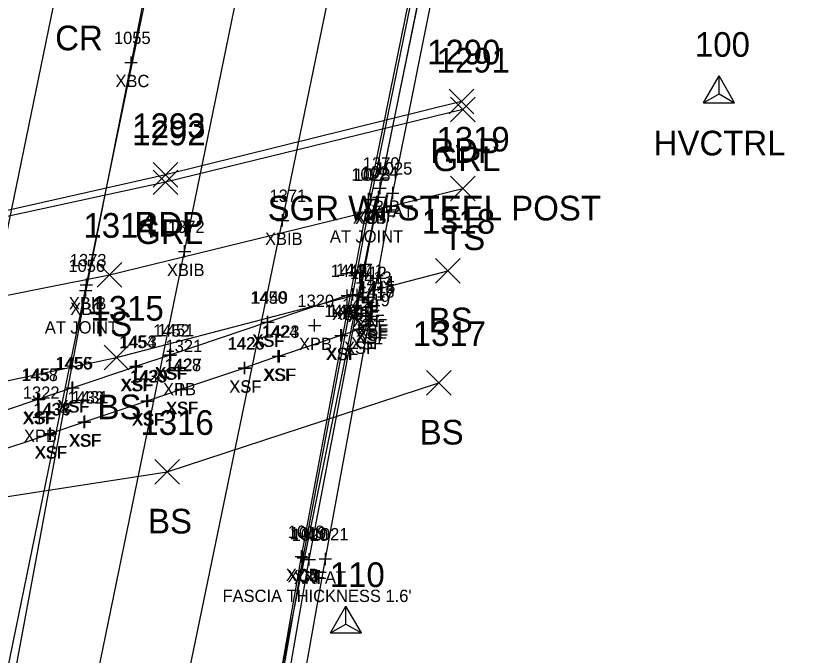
# Model space of a CAD drawing. Extents: x 1683147 to 1683637, y 416837 to 418211.
# Drawn here: x 1683315.4 to 1683379.1, y 417492.2 to 417544.1 of the extents above; entities that cross this region are included whole.
import ezdxf

# ---------------------------------------------------------------- set-up
doc = ezdxf.new("R2010")
doc.units = 0
for name, color, linetype in [('B_A', 7, 'Continuous'), ('B_C', 7, 'Continuous'), ('B_I', 7, 'Continuous'), ('B_TIC', 7, 'Continuous'), ('BB', 7, 'Continuous'), ('BDC', 7, 'Continuous'), ('BDEFAULT', 7, 'Continuous'), ('BELB', 7, 'Continuous'), ('BF', 7, 'Continuous'), ('BR', 7, 'Continuous'), ('C_A', 7, 'Continuous'), ('C_I', 7, 'Continuous'), ('CPSM', 7, 'Continuous'), ('L_A', 7, 'Continuous'), ('L_I', 7, 'Continuous'), ('L_TIC', 7, 'Continuous'), ('LELB', 7, 'Continuous'), ('P_A', 7, 'Continuous'), ('P_I', 7, 'Continuous'), ('P_TIC', 7, 'Continuous'), ('PET', 7, 'Continuous'), ('R_A', 7, 'Continuous'), ('R_C', 7, 'Continuous'), ('R_I', 7, 'Continuous'), ('R_TIC', 7, 'Continuous'), ('RGR', 7, 'Continuous')]:
    doc.layers.add(name, color=color, linetype=linetype)

msp = doc.modelspace()

# ---------------------------------------------------------------- linework, layer by layer
at = {"layer": 'B_TIC'}
for p, q in [((1683324.715, 417540.29), (1683324.791, 417540.29)), ((1683344.921, 417530.101), (1683344.996, 417530.101)), ((1683344.8, 417529.377), (1683344.875, 417529.377)), ((1683345.954, 417529.699), (1683346.03, 417529.699)), ((1683343.975, 417529.208), (1683344.05, 417529.208)), ((1683344.182, 417529.185), (1683344.258, 417529.185)), ((1683337.021, 417527.483), (1683337.096, 417527.483)), ((1683329.062, 417524.964), (1683329.137, 417524.964)), ((1683321.047, 417521.799), (1683321.122, 417521.799)), ((1683321.099, 417522.255), (1683321.175, 417522.255)), ((1683342.26, 417521.384), (1683342.336, 417521.384)), ((1683342.703, 417521.474), (1683342.778, 417521.474)), ((1683343.053, 417521.439), (1683343.129, 417521.439)), ((1683343.053, 417521.439), (1683343.129, 417521.439)), ((1683343.552, 417521.224), (1683343.627, 417521.224)), ((1683343.95, 417520.833), (1683344.026, 417520.833)), ((1683344.15, 417520.48), (1683344.225, 417520.48)), ((1683344.244, 417520.054), (1683344.32, 417520.054)), ((1683335.781, 417519.216), (1683335.857, 417519.216)), ((1683335.822, 417519.23), (1683335.897, 417519.23)), ((1683344.153, 417519.468), (1683344.229, 417519.468)), ((1683344.217, 417519.713), (1683344.293, 417519.713)), ((1683339.608, 417518.956), (1683339.684, 417518.956)), ((1683343.243, 417518.65), (1683343.318, 417518.65)), ((1683343.808, 417519.011), (1683343.883, 417519.011)), ((1683341.749, 417518.142), (1683341.825, 417518.142)), ((1683341.818, 417518.147), (1683341.893, 417518.147)), ((1683327.864, 417516.543), (1683327.939, 417516.543)), ((1683327.935, 417516.576), (1683328.01, 417516.576)), ((1683336.669, 417516.454), (1683336.745, 417516.454)), ((1683336.761, 417516.455), (1683336.837, 417516.455)), ((1683325.085, 417515.608), (1683325.16, 417515.608)), ((1683325.172, 417515.648), (1683325.248, 417515.648)), ((1683333.924, 417515.49), (1683333.999, 417515.49)), ((1683333.939, 417515.509), (1683334.015, 417515.509)), ((1683328.581, 417515.289), (1683328.656, 417515.289)), ((1683319.943, 417513.882), (1683320.018, 417513.882)), ((1683320, 417513.899), (1683320.075, 417513.899)), ((1683328.774, 417513.745), (1683328.85, 417513.745)), ((1683328.825, 417513.773), (1683328.9, 417513.773)), ((1683317.155, 417512.94), (1683317.23, 417512.94)), ((1683317.244, 417512.976), (1683317.32, 417512.976)), ((1683326.011, 417512.818), (1683326.087, 417512.818)), ((1683326.076, 417512.847), (1683326.152, 417512.847)), ((1683317.287, 417511.503), (1683317.363, 417511.503)), ((1683320.9, 417511.111), (1683320.976, 417511.111)), ((1683320.968, 417511.137), (1683321.043, 417511.137)), ((1683318.125, 417510.144), (1683318.201, 417510.144)), ((1683318.184, 417510.177), (1683318.259, 417510.177)), ((1683338.542, 417500.213), (1683338.617, 417500.213)), ((1683338.695, 417500.106), (1683338.77, 417500.106)), ((1683339.173, 417499.968), (1683339.249, 417499.968)), ((1683340.486, 417500.015), (1683340.561, 417500.015))]:
    msp.add_line(p, q, dxfattribs=at)
for points in [[(1683324.212, 417540.29), (1683325.212, 417540.29)], [(1683324.712, 417539.79), (1683324.712, 417540.79)], [(1683344.417, 417530.101), (1683345.417, 417530.101)], [(1683344.917, 417529.601), (1683344.917, 417530.601)], [(1683345.951, 417529.199), (1683345.951, 417530.199)], [(1683343.971, 417528.708), (1683343.971, 417529.708)], [(1683344.179, 417528.685), (1683344.179, 417529.685)], [(1683344.296, 417529.377), (1683345.296, 417529.377)], [(1683344.796, 417528.877), (1683344.796, 417529.877)], [(1683345.451, 417529.699), (1683346.451, 417529.699)], [(1683343.471, 417529.208), (1683344.471, 417529.208)], [(1683343.679, 417529.185), (1683344.679, 417529.185)], [(1683336.517, 417527.483), (1683337.517, 417527.483)], [(1683337.017, 417526.983), (1683337.017, 417527.983)], [(1683328.558, 417524.964), (1683329.558, 417524.964)], [(1683329.058, 417524.464), (1683329.058, 417525.464)], [(1683321.096, 417521.755), (1683321.096, 417522.755)], [(1683320.543, 417521.799), (1683321.543, 417521.799)], [(1683320.596, 417522.255), (1683321.596, 417522.255)], [(1683321.043, 417521.299), (1683321.043, 417522.3)], [(1683342.257, 417520.884), (1683342.257, 417521.884)], [(1683342.699, 417520.974), (1683342.699, 417521.974)], [(1683343.05, 417520.939), (1683343.05, 417521.939)], [(1683343.05, 417520.939), (1683343.05, 417521.939)], [(1683343.548, 417520.724), (1683343.548, 417521.724)], [(1683341.757, 417521.384), (1683342.757, 417521.384)], [(1683342.199, 417521.474), (1683343.199, 417521.474)], [(1683342.55, 417521.439), (1683343.55, 417521.439)], [(1683342.55, 417521.439), (1683343.55, 417521.439)], [(1683343.048, 417521.224), (1683344.048, 417521.224)], [(1683343.947, 417520.333), (1683343.947, 417521.333)], [(1683343.447, 417520.833), (1683344.447, 417520.833)], [(1683343.646, 417520.48), (1683344.646, 417520.48)], [(1683344.146, 417519.98), (1683344.146, 417520.98)], [(1683344.241, 417519.554), (1683344.241, 417520.554)], [(1683343.741, 417520.054), (1683344.741, 417520.054)], [(1683344.15, 417518.968), (1683344.15, 417519.968)], [(1683344.214, 417519.213), (1683344.214, 417520.213)], [(1683335.278, 417519.216), (1683336.278, 417519.216)], [(1683335.318, 417519.23), (1683336.318, 417519.23)], [(1683335.778, 417518.716), (1683335.778, 417519.716)], [(1683335.818, 417518.73), (1683335.818, 417519.73)], [(1683339.605, 417518.456), (1683339.605, 417519.456)], [(1683343.239, 417518.15), (1683343.239, 417519.15)], [(1683343.65, 417519.468), (1683344.65, 417519.468)], [(1683343.714, 417519.713), (1683344.714, 417519.713)], [(1683343.804, 417518.511), (1683343.804, 417519.511)], [(1683339.105, 417518.956), (1683340.105, 417518.956)], [(1683341.746, 417517.642), (1683341.746, 417518.642)], [(1683341.814, 417517.647), (1683341.814, 417518.647)], [(1683342.739, 417518.65), (1683343.739, 417518.65)], [(1683343.304, 417519.011), (1683344.304, 417519.011)], [(1683341.246, 417518.142), (1683342.246, 417518.142)], [(1683341.314, 417518.147), (1683342.314, 417518.147)], [(1683327.86, 417516.043), (1683327.86, 417517.043)], [(1683327.931, 417516.076), (1683327.931, 417517.076)], [(1683336.666, 417515.954), (1683336.666, 417516.954)], [(1683336.758, 417515.955), (1683336.758, 417516.955)], [(1683325.081, 417515.108), (1683325.081, 417516.108)], [(1683325.169, 417515.148), (1683325.169, 417516.148)], [(1683327.36, 417516.543), (1683328.36, 417516.543)], [(1683327.431, 417516.576), (1683328.431, 417516.576)], [(1683333.92, 417514.99), (1683333.92, 417515.99)], [(1683333.936, 417515.009), (1683333.936, 417516.009)], [(1683336.166, 417516.454), (1683337.166, 417516.454)], [(1683336.258, 417516.455), (1683337.258, 417516.455)], [(1683324.581, 417515.608), (1683325.581, 417515.608)], [(1683324.669, 417515.648), (1683325.669, 417515.648)], [(1683328.577, 417514.789), (1683328.577, 417515.789)], [(1683333.42, 417515.49), (1683334.42, 417515.49)], [(1683333.436, 417515.509), (1683334.436, 417515.509)], [(1683328.077, 417515.289), (1683329.077, 417515.289)], [(1683319.939, 417513.382), (1683319.939, 417514.382)], [(1683319.996, 417513.399), (1683319.996, 417514.399)], [(1683328.771, 417513.245), (1683328.771, 417514.245)], [(1683328.821, 417513.273), (1683328.821, 417514.273)], [(1683317.151, 417512.44), (1683317.151, 417513.44)], [(1683317.241, 417512.476), (1683317.241, 417513.476)], [(1683319.439, 417513.882), (1683320.439, 417513.882)], [(1683319.496, 417513.899), (1683320.496, 417513.899)], [(1683328.271, 417513.745), (1683329.271, 417513.745)], [(1683328.321, 417513.773), (1683329.321, 417513.773)], [(1683316.651, 417512.94), (1683317.651, 417512.94)], [(1683316.741, 417512.976), (1683317.741, 417512.976)], [(1683325.508, 417512.818), (1683326.508, 417512.818)], [(1683325.573, 417512.847), (1683326.573, 417512.847)], [(1683326.008, 417512.318), (1683326.008, 417513.318)], [(1683326.073, 417512.347), (1683326.073, 417513.347)], [(1683316.784, 417511.503), (1683317.784, 417511.503)], [(1683317.284, 417511.003), (1683317.284, 417512.003)], [(1683320.897, 417510.611), (1683320.897, 417511.611)], [(1683320.964, 417510.637), (1683320.964, 417511.637)], [(1683320.397, 417511.111), (1683321.397, 417511.111)], [(1683320.464, 417511.137), (1683321.464, 417511.137)], [(1683318.122, 417509.644), (1683318.122, 417510.644)], [(1683318.18, 417509.677), (1683318.18, 417510.677)], [(1683317.622, 417510.144), (1683318.622, 417510.144)], [(1683317.68, 417510.177), (1683318.68, 417510.177)], [(1683338.538, 417499.713), (1683338.538, 417500.713)], [(1683338.038, 417500.213), (1683339.039, 417500.213)], [(1683338.191, 417500.106), (1683339.191, 417500.106)], [(1683338.691, 417499.606), (1683338.691, 417500.606)], [(1683339.17, 417499.468), (1683339.17, 417500.468)], [(1683340.482, 417499.515), (1683340.482, 417500.515)], [(1683338.67, 417499.968), (1683339.67, 417499.968)], [(1683339.982, 417500.015), (1683340.982, 417500.015)]]:
    msp.add_lwpolyline(points, dxfattribs=at)
at = {"layer": 'BB'}
for points in [[(1683333.132, 417472.311), (1683344.917, 417530.101), (1683362.571, 417615.987), (1683372.841, 417665.754)], [(1683325.054, 417469.66), (1683337.017, 417527.483), (1683354.652, 417613.017), (1683364.916, 417663.193)], [(1683317.14, 417466.973), (1683329.058, 417524.964), (1683346.642, 417610.64), (1683357.082, 417660.489)], [(1683309.186, 417464.354), (1683321.096, 417522.255), (1683338.804, 417607.952), (1683349.063, 417657.849)], [(1683301.278, 417461.805), (1683313.213, 417519.604), (1683330.806, 417605.15), (1683341.02, 417655.206)]]:
    msp.add_lwpolyline(points, dxfattribs=at)
at = {"layer": 'BDC'}
for points in [[(1683333.304, 417470.244), (1683338.538, 417500.213), (1683343.971, 417529.208), (1683352.82, 417572.627), (1683360.871, 417608.794), (1683368.239, 417640.292), (1683375.271, 417668.797)], [(1683333.421, 417470.087), (1683338.691, 417500.106), (1683344.179, 417529.185), (1683353.021, 417572.522), (1683361.056, 417608.824), (1683368.456, 417640.314), (1683375.425, 417668.718)]]:
    msp.add_lwpolyline(points, dxfattribs=at)
at = {"layer": 'BDEFAULT'}
for points in [[(1683343.05, 417521.439), (1683342.699, 417521.474), (1683342.257, 417521.384), (1683335.818, 417519.23), (1683335.778, 417519.216), (1683327.931, 417516.576), (1683327.86, 417516.543), (1683325.169, 417515.648), (1683325.081, 417515.608), (1683319.996, 417513.899), (1683319.939, 417513.882), (1683317.241, 417512.976), (1683317.151, 417512.94), (1683312.064, 417511.232), (1683312.032, 417511.218), (1683309.331, 417510.339), (1683309.23, 417510.287), (1683304.166, 417508.576), (1683304.099, 417508.554), (1683302.774, 417508.108), (1683302.357, 417507.902), (1683302.04, 417507.66), (1683301.878, 417507.523)], [(1683343.05, 417521.439), (1683343.548, 417521.224), (1683343.947, 417520.833), (1683344.146, 417520.48), (1683344.241, 417520.054), (1683344.214, 417519.713), (1683344.15, 417519.468), (1683343.804, 417519.011), (1683343.239, 417518.65), (1683341.814, 417518.147), (1683341.746, 417518.142), (1683336.758, 417516.455), (1683336.666, 417516.454), (1683333.936, 417515.509), (1683333.92, 417515.49), (1683328.821, 417513.773), (1683328.771, 417513.745), (1683326.073, 417512.847), (1683326.008, 417512.818), (1683320.964, 417511.137), (1683320.897, 417511.111), (1683318.18, 417510.177), (1683318.122, 417510.144), (1683313.037, 417508.445)]]:
    msp.add_lwpolyline(points, dxfattribs=at)
at = {"layer": 'BELB'}
msp.add_lwpolyline([(1683351.52, 417660.937), (1683344.246, 417631.627), (1683337.363, 417600.891), (1683329.97, 417566.982), (1683324.712, 417540.29), (1683321.043, 417521.799), (1683314.399, 417485.977), (1683310.141, 417462.954)], dxfattribs=at)
at = {"layer": 'BF'}
msp.add_lwpolyline([(1683335.135, 417469.913), (1683340.482, 417500.015), (1683345.951, 417529.699), (1683354.55, 417572.582), (1683362.731, 417608.707), (1683370.18, 417640.143), (1683377.137, 417668.385)], dxfattribs=at)
at = {"layer": 'BR'}
msp.add_lwpolyline([(1683332.852, 417463.642), (1683334.015, 417470.201), (1683339.17, 417499.968), (1683344.796, 417529.377), (1683353.624, 417572.765), (1683361.607, 417608.917), (1683368.959, 417640.432), (1683375.993, 417668.687), (1683379.103, 417680.373)], dxfattribs=at)
at = {"layer": 'CPSM'}
for p, q in [((1683371.181, 417537.031), (1683372.431, 417539.196)), ((1683373.681, 417537.031), (1683372.431, 417539.196)), ((1683372.431, 417537.753), (1683372.431, 417539.196)), ((1683371.181, 417537.031), (1683372.431, 417537.753)), ((1683372.431, 417537.753), (1683372.431, 417537.753)), ((1683372.431, 417537.753), (1683373.681, 417537.031)), ((1683371.181, 417537.031), (1683373.681, 417537.031)), ((1683340.905, 417494.008), (1683342.155, 417496.173)), ((1683343.405, 417494.008), (1683342.155, 417496.173)), ((1683342.156, 417494.73), (1683342.155, 417496.173)), ((1683340.905, 417494.008), (1683342.156, 417494.73)), ((1683342.156, 417494.73), (1683342.156, 417494.73)), ((1683342.156, 417494.73), (1683343.405, 417494.008)), ((1683340.905, 417494.008), (1683343.405, 417494.008))]:
    msp.add_line(p, q, dxfattribs=at)
at = {"layer": 'L_TIC'}
for points in [[(1683350.626, 417529.069), (1683352.626, 417531.069)], [(1683352.626, 417529.069), (1683350.626, 417531.069)], [(1683349.433, 417522.399), (1683351.433, 417524.399)], [(1683351.433, 417522.399), (1683349.433, 417524.399)], [(1683321.975, 417522.071), (1683323.975, 417524.071)], [(1683323.975, 417522.071), (1683321.975, 417524.071)], [(1683322.546, 417515.347), (1683324.546, 417517.347)], [(1683324.546, 417515.347), (1683322.546, 417517.347)], [(1683348.696, 417513.294), (1683350.696, 417515.294)], [(1683350.696, 417513.294), (1683348.696, 417515.294)], [(1683326.653, 417506.076), (1683328.653, 417508.076)], [(1683328.653, 417506.076), (1683326.653, 417508.076)]]:
    msp.add_lwpolyline(points, dxfattribs=at)
at = {"layer": 'LELB'}
for points in [[(1683205.058, 417500.966), (1683236.725, 417507.171), (1683266.627, 417512.319), (1683295.742, 417517.653), (1683322.975, 417523.071), (1683351.626, 417530.069)], [(1683205.591, 417497.875), (1683237.075, 417504.337), (1683268.914, 417505.721), (1683296.171, 417510.545), (1683323.546, 417516.347), (1683350.433, 417523.399)], [(1683205.213, 417492.626), (1683239.174, 417495.288), (1683270.177, 417500.965), (1683298.559, 417502.586), (1683327.653, 417507.076), (1683349.696, 417514.294)]]:
    msp.add_lwpolyline(points, dxfattribs=at)
at = {"layer": 'P_TIC'}
for points in [[(1683350.521, 417536.139), (1683352.521, 417538.139)], [(1683352.521, 417536.139), (1683350.521, 417538.139)], [(1683326.502, 417530.164), (1683328.502, 417532.164)], [(1683328.502, 417530.164), (1683326.502, 417532.164)]]:
    msp.add_lwpolyline(points, dxfattribs=at)
at = {"layer": 'PET'}
msp.add_lwpolyline([(1683351.521, 417537.139), (1683327.502, 417531.164), (1683310.333, 417527.312), (1683275.263, 417519.769), (1683242.13, 417513.342), (1683204.728, 417507.24)], dxfattribs=at)
at = {"layer": 'R_TIC'}
for points in [[(1683350.634, 417535.475), (1683352.634, 417537.475)], [(1683352.634, 417535.475), (1683350.634, 417537.475)], [(1683326.504, 417529.568), (1683328.504, 417531.568)], [(1683328.504, 417529.568), (1683326.504, 417531.568)]]:
    msp.add_lwpolyline(points, dxfattribs=at)
at = {"layer": 'RGR'}
msp.add_lwpolyline([(1683351.634, 417536.475), (1683327.504, 417530.568), (1683310.27, 417526.858), (1683275.284, 417519.336), (1683242.138, 417513.085), (1683204.773, 417506.832)], dxfattribs=at)

# ---------------------------------------------------------------- texts
at = {"layer": 'B_A'}
for s, p in [('XBC', (1683323.448, 417538.29)), ('XBIB', (1683343.488, 417528.101)), ('XCB', (1683342.708, 417527.208)), ('XCT', (1683342.899, 417527.185)), ('XRF', (1683343.556, 417527.377)), ('XFAT', (1683344.207, 417527.699)), ('XBIB', (1683335.588, 417525.483)), ('XBIB', (1683327.629, 417522.964)), ('XBIB', (1683319.667, 417520.255)), ('XBC', (1683319.779, 417519.799)), ('XSF', (1683341.459, 417519.474)), ('XSF', (1683341.81, 417519.439)), ('XSF', (1683341.81, 417519.439)), ('XSF', (1683341.017, 417519.384)), ('XSF', (1683342.308, 417519.224)), ('XSF', (1683342.707, 417518.833)), ('XSF', (1683342.906, 417518.48)), ('XSF', (1683342.974, 417517.713)), ('XSF', (1683343, 417518.054)), ('XSF', (1683334.538, 417517.216)), ('XSF', (1683334.578, 417517.23)), ('XPB', (1683338.341, 417516.956)), ('XSF', (1683342.564, 417517.011)), ('XSF', (1683342.909, 417517.468)), ('XSF', (1683341.999, 417516.65)), ('XSF', (1683340.506, 417516.142)), ('XSF', (1683340.574, 417516.147)), ('XSF', (1683326.62, 417514.543)), ('XSF', (1683326.691, 417514.576)), ('XSF', (1683335.426, 417514.454)), ('XSF', (1683335.518, 417514.455)), ('XSF', (1683323.841, 417513.608)), ('XSF', (1683323.928, 417513.648)), ('XPB', (1683327.313, 417513.289)), ('XSF', (1683332.68, 417513.49)), ('XSF', (1683332.696, 417513.509)), ('XSF', (1683318.699, 417511.882)), ('XSF', (1683318.756, 417511.899)), ('XSF', (1683327.581, 417511.773)), ('XSF', (1683327.531, 417511.745)), ('XSF', (1683315.911, 417510.94)), ('XSF', (1683316, 417510.976)), ('XSF', (1683324.768, 417510.818)), ('XSF', (1683324.832, 417510.847)), ('XPB', (1683316.02, 417509.503)), ('XSF', (1683319.657, 417509.111)), ('XSF', (1683319.724, 417509.137)), ('XSF', (1683316.881, 417508.144)), ('XSF', (1683316.94, 417508.177)), ('XCB', (1683337.275, 417498.213)), ('XCT', (1683337.412, 417498.106)), ('XRF', (1683337.93, 417497.968)), ('XFAT', (1683338.738, 417498.015))]:
    msp.add_text(s, height=1, dxfattribs=at).set_placement(p)
at = {"layer": 'B_C'}
for s, p in [('AT JOINT', (1683340.852, 417525.685)), ('AT JOINT', (1683317.717, 417518.299)), ("FASCIA THICKNESS 1.6'", (1683332.136, 417496.515))]:
    msp.add_text(s, height=1, dxfattribs=at).set_placement(p)
at = {"layer": 'B_I'}
for s, p in [('1055', (1683323.326, 417541.79)), ('1370', (1683343.527, 417531.601)), ('1025', (1683344.565, 417531.199)), ('1022', (1683342.586, 417530.708)), ('1023', (1683342.793, 417530.685)), ('1024', (1683343.411, 417530.877)), ('1371', (1683335.954, 417528.983)), ('1372', (1683327.712, 417526.464)), ('1056', (1683319.63, 417523.299)), ('1373', (1683319.749, 417523.755)), ('1448', (1683340.91, 417522.884)), ('1447', (1683341.353, 417522.974)), ('1411', (1683342.27, 417522.939)), ('1411', (1683342.27, 417522.939)), ('1412', (1683342.486, 417522.724)), ('1413', (1683342.884, 417522.333)), ('1414', (1683343.083, 417521.98)), ('1415', (1683343.178, 417521.554)), ('1450', (1683334.388, 417520.716)), ('1449', (1683334.468, 417520.73)), ('1417', (1683343.087, 417520.968)), ('1416', (1683343.124, 417521.213)), ('1320', (1683338.215, 417520.456)), ('1420', (1683341.85, 417520.15)), ('1419', (1683342.738, 417520.511)), ('1422', (1683340.4, 417519.642)), ('1421', (1683340.752, 417519.647)), ('1452', (1683326.514, 417518.043)), ('1451', (1683326.868, 417518.076)), ('1424', (1683335.32, 417517.954)), ('1423', (1683335.411, 417517.955)), ('1454', (1683323.735, 417517.108)), ('1453', (1683323.822, 417517.148)), ('1426', (1683332.546, 417516.99)), ('1425', (1683332.59, 417517.009)), ('1321', (1683327.514, 417516.789)), ('1456', (1683318.565, 417515.382)), ('1455', (1683318.65, 417515.399)), ('1428', (1683327.424, 417515.245)), ('1427', (1683327.475, 417515.273)), ('1458', (1683315.805, 417514.44)), ('1457', (1683315.894, 417514.476)), ('1430', (1683324.618, 417514.318)), ('1429', (1683324.722, 417514.347)), ('1322', (1683315.937, 417513.003)), ('1432', (1683319.55, 417512.611)), ('1431', (1683319.901, 417512.637)), ('1434', (1683316.775, 417511.644)), ('1433', (1683316.834, 417511.677)), ('1018', (1683337.436, 417501.713)), ('1019', (1683337.585, 417501.606)), ('1020', (1683337.741, 417501.468)), ('1021', (1683339.38, 417501.515))]:
    msp.add_text(s, height=1, dxfattribs=at).set_placement(p)
at = {"layer": 'C_A'}
msp.add_text('HVCTRL', height=2, dxfattribs=at).set_placement((1683367.124, 417532.753))
at = {"layer": 'C_I'}
for s, p in [('100', (1683370.471, 417540.753)), ('110', (1683340.841, 417497.73))]:
    msp.add_text(s, height=2, dxfattribs=at).set_placement(p)
at = {"layer": 'L_A'}
for s, p in [('TS', (1683350.036, 417525.069)), ('BS', (1683348.874, 417518.399)), ('TS', (1683321.385, 417518.071)), ('BS', (1683321.987, 417511.347)), ('BS', (1683348.137, 417509.294)), ('BS', (1683326.094, 417502.076))]:
    msp.add_text(s, height=2, dxfattribs=at).set_placement(p)
at = {"layer": 'L_I'}
for s, p in [('1319', (1683349.493, 417533.069)), ('1314', (1683320.849, 417526.071)), ('1318', (1683348.307, 417526.399)), ('1315', (1683321.42, 417519.347)), ('1317', (1683347.57, 417517.294)), ('1316', (1683325.473, 417510.076))]:
    msp.add_text(s, height=2, dxfattribs=at).set_placement(p)
at = {"layer": 'P_A'}
for s, p in [('CR', (1683318.557, 417541.282)), ('RDP', (1683349.009, 417532.139)), ('RDP', (1683324.99, 417526.164))]:
    msp.add_text(s, height=2, dxfattribs=at).set_placement(p)
at = {"layer": 'P_I'}
for s, p in [('1290', (1683348.742, 417540.139)), ('1293', (1683324.809, 417534.164))]:
    msp.add_text(s, height=2, dxfattribs=at).set_placement(p)
at = {"layer": 'R_A'}
for p in [(1683349.178, 417531.475), (1683325.048, 417525.568)]:
    msp.add_text('GRL', height=2, dxfattribs=at).set_placement(p)
at = {"layer": 'R_C'}
msp.add_text('SGR W/ STEEL POST', height=2, dxfattribs=at).set_placement((1683335.8, 417527.475))
at = {"layer": 'R_I'}
for s, p in [('1291', (1683349.509, 417539.475)), ('1292', (1683324.812, 417533.568))]:
    msp.add_text(s, height=2, dxfattribs=at).set_placement(p)

doc.saveas('drawing.dxf')
